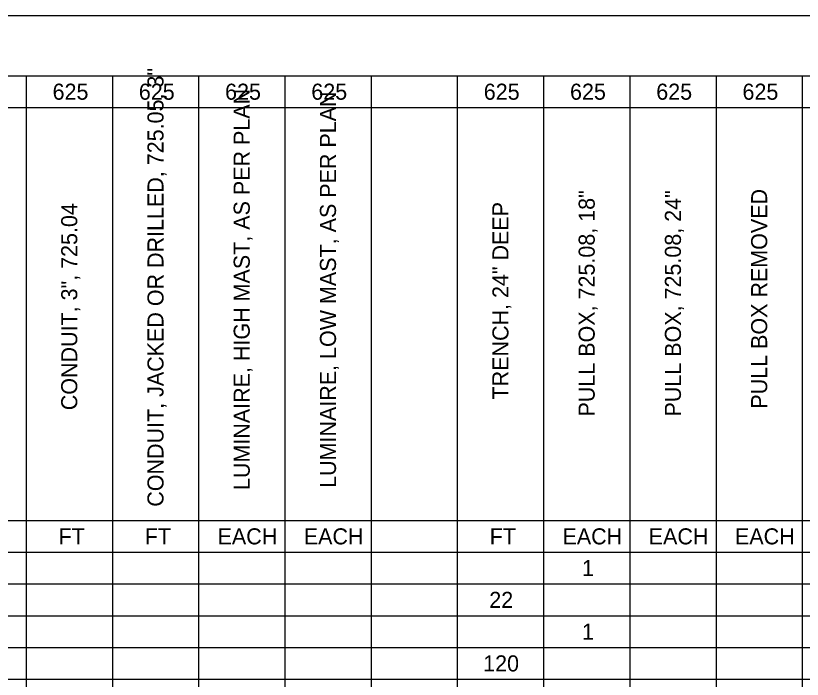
# Model space of a CAD drawing. Extents: x 0 to 34, y 0 to 22.
# Drawn here: x 19.72 to 26.26, y 16.48 to 22 of the extents above; entities that cross this region are included whole.
import ezdxf

# ---------------------------------------------------------------- set-up
doc = ezdxf.new("R2010")
doc.units = 0
for name, color, linetype in [('SH_Border', 7, 'Continuous'), ('SH_Cut_Line', 7, 'Continuous'), ('SH_Text', 7, 'Continuous')]:
    doc.layers.add(name, color=color, linetype=linetype)

msp = doc.modelspace()

# ---------------------------------------------------------------- linework, layer by layer
at = {"layer": 'SH_Border'}
msp.add_lwpolyline([(1.5, 21.5), (33.5, 21.5), (33.5, 0.5), (1.5, 0.5)], close=True, dxfattribs=at)
at = {"layer": 'SH_Cut_Line'}
msp.add_lwpolyline([(0, 0), (34, 0), (34, 22), (0, 22)], close=True, dxfattribs=at)
at = {"layer": 'SH_Text'}
for p, q in [((15.5038, 21.5001), (21.9583, 21.5001)), ((19.8068, 21.5001), (19.8068, 21.2359)), ((20.524, 21.5001), (20.524, 21.2359)), ((21.2412, 21.5001), (21.2412, 21.2359)), ((21.9583, 21.5001), (22.6755, 21.5001)), ((21.9583, 21.5001), (21.9583, 21.2359)), ((22.6755, 21.5001), (24.827, 21.5001)), ((22.6755, 21.5001), (22.6755, 21.2359)), ((23.3927, 21.5001), (23.3927, 21.2359)), ((24.1099, 21.5001), (24.1099, 21.2359)), ((24.827, 21.5001), (25.5442, 21.5001)), ((24.827, 21.5001), (24.827, 21.2359)), ((25.5442, 21.5001), (26.2614, 21.5001)), ((25.5442, 21.5001), (25.5442, 21.2359)), ((26.2614, 21.5001), (28.4129, 21.5001)), ((26.2614, 21.5001), (26.2614, 21.2359)), ((15.5038, 21.2359), (21.9583, 21.2359)), ((19.8068, 21.2359), (19.8068, 20.9716)), ((20.524, 21.2359), (20.524, 20.9716)), ((21.2412, 21.2359), (21.2412, 20.9716)), ((21.9583, 21.2359), (22.6755, 21.2359)), ((21.9583, 21.2359), (21.9583, 20.9716)), ((22.6755, 21.2359), (24.827, 21.2359)), ((22.6755, 21.2359), (22.6755, 20.9716)), ((23.3927, 21.2359), (23.3927, 20.9716)), ((24.1099, 21.2359), (24.1099, 20.9716)), ((24.827, 21.2359), (25.5442, 21.2359)), ((24.827, 21.2359), (24.827, 20.9716)), ((25.5442, 21.2359), (26.2614, 21.2359)), ((25.5442, 21.2359), (25.5442, 20.9716)), ((26.2614, 21.2359), (28.4129, 21.2359)), ((26.2614, 21.2359), (26.2614, 20.9716)), ((19.8068, 20.9716), (19.8068, 20.7074)), ((20.524, 20.9716), (20.524, 20.7074)), ((21.2412, 20.9716), (21.2412, 20.7074)), ((21.9583, 20.9716), (21.9583, 20.7074)), ((22.6755, 20.9716), (22.6755, 20.7074)), ((23.3927, 20.9716), (23.3927, 20.7074)), ((24.1099, 20.9716), (24.1099, 20.7074)), ((24.827, 20.9716), (24.827, 20.7074)), ((25.5442, 20.9716), (25.5442, 20.7074)), ((26.2614, 20.9716), (26.2614, 20.7074)), ((19.8068, 20.7074), (19.8068, 20.4432)), ((20.524, 20.7074), (20.524, 20.4432)), ((21.2412, 20.7074), (21.2412, 20.4432)), ((21.9583, 20.7074), (21.9583, 20.4432)), ((22.6755, 20.7074), (22.6755, 20.4432)), ((23.3927, 20.7074), (23.3927, 20.4432)), ((24.1099, 20.7074), (24.1099, 20.4432)), ((24.827, 20.7074), (24.827, 20.4432)), ((25.5442, 20.7074), (25.5442, 20.4432)), ((26.2614, 20.7074), (26.2614, 20.4432)), ((19.8068, 20.4432), (19.8068, 20.179)), ((20.524, 20.4432), (20.524, 20.179)), ((21.2412, 20.4432), (21.2412, 20.179)), ((21.9583, 20.4432), (21.9583, 20.179)), ((22.6755, 20.4432), (22.6755, 20.179)), ((23.3927, 20.4432), (23.3927, 20.179)), ((24.1099, 20.4432), (24.1099, 20.179)), ((24.827, 20.4432), (24.827, 20.179)), ((25.5442, 20.4432), (25.5442, 20.179)), ((26.2614, 20.4432), (26.2614, 20.179)), ((19.8068, 20.179), (19.8068, 19.9147)), ((20.524, 20.179), (20.524, 19.9147)), ((21.2412, 20.179), (21.2412, 19.9147)), ((21.9583, 20.179), (21.9583, 19.9147)), ((22.6755, 20.179), (22.6755, 19.9147)), ((23.3927, 20.179), (23.3927, 19.9147)), ((24.1099, 20.179), (24.1099, 19.9147)), ((24.827, 20.179), (24.827, 19.9147)), ((25.5442, 20.179), (25.5442, 19.9147)), ((26.2614, 20.179), (26.2614, 19.9147)), ((19.8068, 19.9147), (19.8068, 19.6505)), ((20.524, 19.9147), (20.524, 19.6505)), ((21.2412, 19.9147), (21.2412, 19.6505)), ((21.9583, 19.9147), (21.9583, 19.6505)), ((22.6755, 19.9147), (22.6755, 19.6505)), ((23.3927, 19.9147), (23.3927, 19.6505)), ((24.1099, 19.9147), (24.1099, 19.6505)), ((24.827, 19.9147), (24.827, 19.6505)), ((25.5442, 19.9147), (25.5442, 19.6505)), ((26.2614, 19.9147), (26.2614, 19.6505)), ((19.8068, 19.6505), (19.8068, 19.3863)), ((20.524, 19.6505), (20.524, 19.3863)), ((21.2412, 19.6505), (21.2412, 19.3863)), ((21.9583, 19.6505), (21.9583, 19.3863)), ((22.6755, 19.6505), (22.6755, 19.3863)), ((23.3927, 19.6505), (23.3927, 19.3863)), ((24.1099, 19.6505), (24.1099, 19.3863)), ((24.827, 19.6505), (24.827, 19.3863)), ((25.5442, 19.6505), (25.5442, 19.3863)), ((26.2614, 19.6505), (26.2614, 19.3863)), ((19.8068, 19.3863), (19.8068, 19.1221)), ((20.524, 19.3863), (20.524, 19.1221)), ((21.2412, 19.3863), (21.2412, 19.1221)), ((21.9583, 19.3863), (21.9583, 19.1221)), ((22.6755, 19.3863), (22.6755, 19.1221)), ((23.3927, 19.3863), (23.3927, 19.1221)), ((24.1099, 19.3863), (24.1099, 19.1221)), ((24.827, 19.3863), (24.827, 19.1221)), ((25.5442, 19.3863), (25.5442, 19.1221)), ((26.2614, 19.3863), (26.2614, 19.1221)), ((19.8068, 19.1221), (19.8068, 18.8579)), ((20.524, 19.1221), (20.524, 18.8579)), ((21.2412, 19.1221), (21.2412, 18.8579)), ((21.9583, 19.1221), (21.9583, 18.8579)), ((22.6755, 19.1221), (22.6755, 18.8579)), ((23.3927, 19.1221), (23.3927, 18.8579)), ((24.1099, 19.1221), (24.1099, 18.8579)), ((24.827, 19.1221), (24.827, 18.8579)), ((25.5442, 19.1221), (25.5442, 18.8579)), ((26.2614, 19.1221), (26.2614, 18.8579)), ((19.8068, 18.8579), (19.8068, 18.5936)), ((20.524, 18.8579), (20.524, 18.5936)), ((21.2412, 18.8579), (21.2412, 18.5936)), ((21.9583, 18.8579), (21.9583, 18.5936)), ((22.6755, 18.8579), (22.6755, 18.5936)), ((23.3927, 18.8579), (23.3927, 18.5936)), ((24.1099, 18.8579), (24.1099, 18.5936)), ((24.827, 18.8579), (24.827, 18.5936)), ((25.5442, 18.8579), (25.5442, 18.5936)), ((26.2614, 18.8579), (26.2614, 18.5936)), ((19.8068, 18.5936), (19.8068, 18.3294)), ((20.524, 18.5936), (20.524, 18.3294)), ((21.2412, 18.5936), (21.2412, 18.3294)), ((21.9583, 18.5936), (21.9583, 18.3294)), ((22.6755, 18.5936), (22.6755, 18.3294)), ((23.3927, 18.5936), (23.3927, 18.3294)), ((24.1099, 18.5936), (24.1099, 18.3294)), ((24.827, 18.5936), (24.827, 18.3294)), ((25.5442, 18.5936), (25.5442, 18.3294)), ((26.2614, 18.5936), (26.2614, 18.3294)), ((19.8068, 18.3294), (19.8068, 18.0652)), ((20.524, 18.3294), (20.524, 18.0652)), ((21.2412, 18.3294), (21.2412, 18.0652)), ((21.9583, 18.3294), (21.9583, 18.0652)), ((22.6755, 18.3294), (22.6755, 18.0652)), ((23.3927, 18.3294), (23.3927, 18.0652)), ((24.1099, 18.3294), (24.1099, 18.0652)), ((24.827, 18.3294), (24.827, 18.0652)), ((25.5442, 18.3294), (25.5442, 18.0652)), ((26.2614, 18.3294), (26.2614, 18.0652)), ((19.8068, 18.0652), (19.8068, 17.801)), ((20.524, 18.0652), (20.524, 17.801)), ((21.2412, 18.0652), (21.2412, 17.801)), ((21.9583, 18.0652), (21.9583, 17.801)), ((22.6755, 18.0652), (22.6755, 17.801)), ((23.3927, 18.0652), (23.3927, 17.801)), ((24.1099, 18.0652), (24.1099, 17.801)), ((24.827, 18.0652), (24.827, 17.801)), ((25.5442, 18.0652), (25.5442, 17.801)), ((26.2614, 18.0652), (26.2614, 17.801)), ((15.5038, 17.801), (21.9583, 17.801)), ((19.8068, 17.801), (19.8068, 17.5367)), ((20.524, 17.801), (20.524, 17.5367)), ((21.2412, 17.801), (21.2412, 17.5367)), ((21.9583, 17.801), (22.6755, 17.801)), ((21.9583, 17.801), (21.9583, 17.5367)), ((22.6755, 17.801), (24.827, 17.801)), ((22.6755, 17.801), (22.6755, 17.5367)), ((23.3927, 17.801), (23.3927, 17.5367)), ((24.1099, 17.801), (24.1099, 17.5367)), ((24.827, 17.801), (25.5442, 17.801)), ((24.827, 17.801), (24.827, 17.5367)), ((25.5442, 17.801), (26.2614, 17.801)), ((25.5442, 17.801), (25.5442, 17.5367)), ((26.2614, 17.801), (28.4129, 17.801)), ((26.2614, 17.801), (26.2614, 17.5367)), ((15.5038, 17.5367), (21.9583, 17.5367)), ((19.8068, 17.5367), (19.8068, 17.2725)), ((20.524, 17.5367), (20.524, 17.2725)), ((21.2412, 17.5367), (21.2412, 17.2725)), ((21.9583, 17.5367), (22.6755, 17.5367)), ((21.9583, 17.5367), (21.9583, 17.2725)), ((22.6755, 17.5367), (24.827, 17.5367)), ((22.6755, 17.5367), (22.6755, 17.2725)), ((23.3927, 17.5367), (23.3927, 17.2725)), ((24.1099, 17.5367), (24.1099, 17.2725)), ((24.827, 17.5367), (25.5442, 17.5367)), ((24.827, 17.5367), (24.827, 17.2725)), ((25.5442, 17.5367), (26.2614, 17.5367)), ((25.5442, 17.5367), (25.5442, 17.2725)), ((26.2614, 17.5367), (28.4129, 17.5367)), ((26.2614, 17.5367), (26.2614, 17.2725)), ((15.5038, 17.2725), (21.9583, 17.2725)), ((19.8068, 17.2725), (19.8068, 17.0083)), ((20.524, 17.2725), (20.524, 17.0083)), ((21.2412, 17.2725), (21.2412, 17.0083)), ((21.9583, 17.2725), (22.6755, 17.2725)), ((21.9583, 17.2725), (21.9583, 17.0083)), ((22.6755, 17.2725), (24.827, 17.2725)), ((22.6755, 17.2725), (22.6755, 17.0083)), ((23.3927, 17.2725), (23.3927, 17.0083)), ((24.1099, 17.2725), (24.1099, 17.0083)), ((24.827, 17.2725), (25.5442, 17.2725)), ((24.827, 17.2725), (24.827, 17.0083)), ((25.5442, 17.2725), (26.2614, 17.2725)), ((25.5442, 17.2725), (25.5442, 17.0083)), ((26.2614, 17.2725), (28.4129, 17.2725)), ((26.2614, 17.2725), (26.2614, 17.0083)), ((15.5038, 17.0083), (21.9583, 17.0083)), ((19.8068, 17.0083), (19.8068, 16.7441)), ((20.524, 17.0083), (20.524, 16.7441)), ((21.2412, 17.0083), (21.2412, 16.7441)), ((21.9583, 17.0083), (22.6755, 17.0083)), ((21.9583, 17.0083), (21.9583, 16.7441)), ((22.6755, 17.0083), (24.827, 17.0083)), ((22.6755, 17.0083), (22.6755, 16.7441)), ((23.3927, 17.0083), (23.3927, 16.7441)), ((24.1099, 17.0083), (24.1099, 16.7441)), ((24.827, 17.0083), (25.5442, 17.0083)), ((24.827, 17.0083), (24.827, 16.7441)), ((25.5442, 17.0083), (26.2614, 17.0083)), ((25.5442, 17.0083), (25.5442, 16.7441)), ((26.2614, 17.0083), (28.4129, 17.0083)), ((26.2614, 17.0083), (26.2614, 16.7441)), ((15.5038, 16.7441), (21.9583, 16.7441)), ((19.8068, 16.7441), (19.8068, 16.4799)), ((20.524, 16.7441), (20.524, 16.4799)), ((21.2412, 16.7441), (21.2412, 16.4799)), ((21.9583, 16.7441), (22.6755, 16.7441)), ((21.9583, 16.7441), (21.9583, 16.4799)), ((22.6755, 16.7441), (24.827, 16.7441)), ((22.6755, 16.7441), (22.6755, 16.4799)), ((23.3927, 16.7441), (23.3927, 16.4799)), ((24.1099, 16.7441), (24.1099, 16.4799)), ((24.827, 16.7441), (25.5442, 16.7441)), ((24.827, 16.7441), (24.827, 16.4799)), ((25.5442, 16.7441), (26.2614, 16.7441)), ((25.5442, 16.7441), (25.5442, 16.4799)), ((26.2614, 16.7441), (28.4129, 16.7441)), ((26.2614, 16.7441), (26.2614, 16.4799)), ((15.5038, 16.4799), (21.9583, 16.4799)), ((19.8068, 16.4799), (19.8068, 16.2156)), ((20.524, 16.4799), (20.524, 16.2156)), ((21.2412, 16.4799), (21.2412, 16.2156)), ((21.9583, 16.4799), (22.6755, 16.4799)), ((21.9583, 16.4799), (21.9583, 16.2156)), ((22.6755, 16.4799), (24.827, 16.4799)), ((22.6755, 16.4799), (22.6755, 16.2156)), ((23.3927, 16.4799), (23.3927, 16.2156)), ((24.1099, 16.4799), (24.1099, 16.2156)), ((24.827, 16.4799), (25.5442, 16.4799)), ((24.827, 16.4799), (24.827, 16.2156)), ((25.5442, 16.4799), (26.2614, 16.4799)), ((25.5442, 16.4799), (25.5442, 16.2156)), ((26.2614, 16.4799), (28.4129, 16.4799)), ((26.2614, 16.4799), (26.2614, 16.2156))]:
    msp.add_line(p, q, dxfattribs=at)

# ---------------------------------------------------------------- texts
for s, p in [('CONDUIT, JACKED OR DRILLED, 725.05, 3"', (20.9494, 17.9154)), ('LUMINAIRE, HIGH MAST, AS PER PLAN', (21.6666, 18.0541)), ('LUMINAIRE, LOW MAST, AS PER PLAN', (22.3838, 18.072)), ('PULL BOX, 725.08, 18"', (24.5353, 18.6659)), ('PULL BOX, 725.08, 24"', (25.2525, 18.6659)), ('PULL BOX REMOVED', (25.9696, 18.7311)), ('CONDUIT, 3", 725.04', (20.2322, 18.7181)), ('TRENCH, 24" DEEP', (23.8181, 18.8076))]:
    msp.add_text(s, height=0.133684, rotation=90, dxfattribs=at).set_placement(p)
for s, height, p in [('625', 0.13368, (20.0269, 21.3011)), ('625', 0.13368, (20.7441, 21.3011)), ('625', 0.13368, (21.4613, 21.3011)), ('625', 0.13368, (22.1784, 21.3011)), ('625', 0.13368, (23.6128, 21.3011)), ('625', 0.13368, (24.3299, 21.3011)), ('625', 0.13368, (25.0471, 21.3011)), ('625', 0.13368, (25.7643, 21.3011)), ('FT', 0.13368, (20.0764, 17.602)), ('FT', 0.13368, (20.7936, 17.602)), ('EACH', 0.13368, (21.3987, 17.602)), ('EACH', 0.13368, (22.1158, 17.602)), ('FT', 0.13368, (23.6623, 17.602)), ('EACH', 0.13368, (24.2674, 17.602)), ('EACH', 0.13368, (24.9845, 17.602)), ('EACH', 0.13368, (25.7017, 17.602)), ('1', 0.1337, (24.4291, 17.3378)), ('22', 0.13368, (23.6584, 17.0736)), ('1', 0.1337, (24.4291, 16.8093)), ('120', 0.13368, (23.6075, 16.5451))]:
    msp.add_text(s, height=height, dxfattribs=at).set_placement(p)

doc.saveas('drawing.dxf')
